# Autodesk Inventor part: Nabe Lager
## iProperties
Author: 42964
Shininess: 10.0
PropertySet Name: _Private Model Information
Length Units: 11269
Angle Units: 11283
Time Units: 11279
Mass Units: 11290
Length Display Precision: 3
Angle Display Precision: 2
Compacted: False
Created: 2000-11
Part Number: Nabe Lager
Document SubType Name: Modeling
Designer: 42964
Control State: 0
Master: False
Checked Out: False
PropertySet Name: Design Tracking Control
Density: 0.0
Volumn: 0.0
Area: 0.0
PropertySet Name: Model Information
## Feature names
1. Extrusion1
2. Extrusion2
3. Revolution1
4. Extrusion3
5. Circular Pattern1
6. Extrusion4
7. Circular Pattern2
8. Revolution2
9. Fillet1
10. Mirror1
